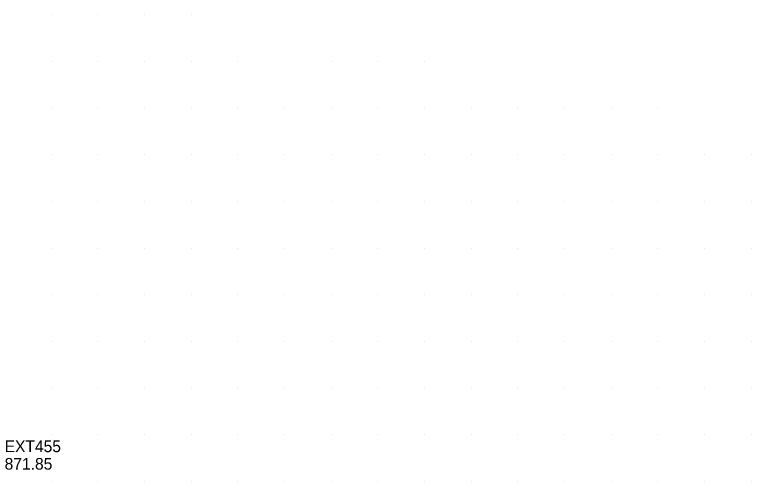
# Model space of a CAD drawing. Extents: x 1762120 to 1766775, y 709485 to 712965.
# Drawn here: x 1762642.2 to 1762800, y 712730 to 712830 of the extents above; entities that cross this region are included whole.
import ezdxf

# ---------------------------------------------------------------- set-up
doc = ezdxf.new("R2010")
doc.units = 0
for name, color, linetype in [('Exist DTM Breakline Cogo Elevation', 7, 'Continuous'), ('Exist DTM Breakline Cogo Number', 7, 'Continuous'), ('Exist DTM QL2 LIDAR Elevation Point', 7, 'Continuous')]:
    doc.layers.add(name, color=color, linetype=linetype)

msp = doc.modelspace()

# ---------------------------------------------------------------- linework, layer by layer
at = {"layer": 'Exist DTM QL2 LIDAR Elevation Point'}
for p, q in [((1762650, 712830), (1762650, 712830)), ((1762660, 712830), (1762660, 712830)), ((1762670, 712830), (1762670, 712830)), ((1762680, 712830), (1762680, 712830)), ((1762650, 712820), (1762650, 712820)), ((1762660, 712820), (1762660, 712820)), ((1762670, 712820), (1762670, 712820)), ((1762680, 712820), (1762680, 712820)), ((1762690, 712820), (1762690, 712820)), ((1762710, 712820), (1762710, 712820)), ((1762720, 712820), (1762720, 712820)), ((1762730, 712820), (1762730, 712820)), ((1762650, 712810), (1762650, 712810)), ((1762660, 712810), (1762660, 712810)), ((1762670, 712810), (1762670, 712810)), ((1762680, 712810), (1762680, 712810)), ((1762690, 712810), (1762690, 712810)), ((1762700, 712810), (1762700, 712810)), ((1762710, 712810), (1762710, 712810)), ((1762720, 712810), (1762720, 712810)), ((1762730, 712810), (1762730, 712810)), ((1762740, 712810), (1762740, 712810)), ((1762750, 712810), (1762750, 712810)), ((1762760, 712810), (1762760, 712810)), ((1762770, 712810), (1762770, 712810)), ((1762780, 712810), (1762780, 712810)), ((1762650, 712800), (1762650, 712800)), ((1762660, 712800), (1762660, 712800)), ((1762670, 712800), (1762670, 712800)), ((1762680, 712800), (1762680, 712800)), ((1762690, 712800), (1762690, 712800)), ((1762700, 712800), (1762700, 712800)), ((1762710, 712800), (1762710, 712800)), ((1762720, 712800), (1762720, 712800)), ((1762730, 712800), (1762730, 712800)), ((1762740, 712800), (1762740, 712800)), ((1762750, 712800), (1762750, 712800)), ((1762760, 712800), (1762760, 712800)), ((1762770, 712800), (1762770, 712800)), ((1762780, 712800), (1762780, 712800)), ((1762790, 712800), (1762790, 712800)), ((1762800, 712800), (1762800, 712800)), ((1762650, 712790), (1762650, 712790)), ((1762660, 712790), (1762660, 712790)), ((1762670, 712790), (1762670, 712790)), ((1762680, 712790), (1762680, 712790)), ((1762690, 712790), (1762690, 712790)), ((1762700, 712790), (1762700, 712790)), ((1762710, 712790), (1762710, 712790)), ((1762720, 712790), (1762720, 712790)), ((1762730, 712790), (1762730, 712790)), ((1762740, 712790), (1762740, 712790)), ((1762750, 712790), (1762750, 712790)), ((1762760, 712790), (1762760, 712790)), ((1762770, 712790), (1762770, 712790)), ((1762780, 712790), (1762780, 712790)), ((1762790, 712790), (1762790, 712790)), ((1762800, 712790), (1762800, 712790)), ((1762650, 712780), (1762650, 712780)), ((1762660, 712780), (1762660, 712780)), ((1762670, 712780), (1762670, 712780)), ((1762680, 712780), (1762680, 712780)), ((1762690, 712780), (1762690, 712780)), ((1762700, 712780), (1762700, 712780)), ((1762710, 712780), (1762710, 712780)), ((1762720, 712780), (1762720, 712780)), ((1762730, 712780), (1762730, 712780)), ((1762740, 712780), (1762740, 712780)), ((1762750, 712780), (1762750, 712780)), ((1762760, 712780), (1762760, 712780)), ((1762770, 712780), (1762770, 712780)), ((1762780, 712780), (1762780, 712780)), ((1762790, 712780), (1762790, 712780)), ((1762800, 712780), (1762800, 712780)), ((1762650, 712770), (1762650, 712770)), ((1762660, 712770), (1762660, 712770)), ((1762670, 712770), (1762670, 712770)), ((1762680, 712770), (1762680, 712770)), ((1762690, 712770), (1762690, 712770)), ((1762700, 712770), (1762700, 712770)), ((1762710, 712770), (1762710, 712770)), ((1762720, 712770), (1762720, 712770)), ((1762730, 712770), (1762730, 712770)), ((1762740, 712770), (1762740, 712770)), ((1762750, 712770), (1762750, 712770)), ((1762760, 712770), (1762760, 712770)), ((1762770, 712770), (1762770, 712770)), ((1762780, 712770), (1762780, 712770)), ((1762790, 712770), (1762790, 712770)), ((1762800, 712770), (1762800, 712770)), ((1762650, 712760), (1762650, 712760)), ((1762660, 712760), (1762660, 712760)), ((1762670, 712760), (1762670, 712760)), ((1762680, 712760), (1762680, 712760)), ((1762690, 712760), (1762690, 712760)), ((1762700, 712760), (1762700, 712760)), ((1762710, 712760), (1762710, 712760)), ((1762720, 712760), (1762720, 712760)), ((1762730, 712760), (1762730, 712760)), ((1762740, 712760), (1762740, 712760)), ((1762750, 712760), (1762750, 712760)), ((1762760, 712760), (1762760, 712760)), ((1762770, 712760), (1762770, 712760)), ((1762780, 712760), (1762780, 712760)), ((1762790, 712760), (1762790, 712760)), ((1762800, 712760), (1762800, 712760)), ((1762650, 712750), (1762650, 712750)), ((1762660, 712750), (1762660, 712750)), ((1762670, 712750), (1762670, 712750)), ((1762680, 712750), (1762680, 712750)), ((1762690, 712750), (1762690, 712750)), ((1762700, 712750), (1762700, 712750)), ((1762710, 712750), (1762710, 712750)), ((1762720, 712750), (1762720, 712750)), ((1762730, 712750), (1762730, 712750)), ((1762740, 712750), (1762740, 712750)), ((1762750, 712750), (1762750, 712750)), ((1762760, 712750), (1762760, 712750)), ((1762770, 712750), (1762770, 712750)), ((1762780, 712750), (1762780, 712750)), ((1762790, 712750), (1762790, 712750)), ((1762800, 712750), (1762800, 712750)), ((1762650, 712740), (1762650, 712740)), ((1762660, 712740), (1762660, 712740)), ((1762670, 712740), (1762670, 712740)), ((1762680, 712740), (1762680, 712740)), ((1762690, 712740), (1762690, 712740)), ((1762700, 712740), (1762700, 712740)), ((1762710, 712740), (1762710, 712740)), ((1762720, 712740), (1762720, 712740)), ((1762730, 712740), (1762730, 712740)), ((1762740, 712740), (1762740, 712740)), ((1762750, 712740), (1762750, 712740)), ((1762760, 712740), (1762760, 712740)), ((1762770, 712740), (1762770, 712740)), ((1762780, 712740), (1762780, 712740)), ((1762790, 712740), (1762790, 712740)), ((1762800, 712740), (1762800, 712740)), ((1762650, 712730), (1762650, 712730)), ((1762660, 712730), (1762660, 712730)), ((1762670, 712730), (1762670, 712730)), ((1762680, 712730), (1762680, 712730)), ((1762690, 712730), (1762690, 712730)), ((1762700, 712730), (1762700, 712730)), ((1762710, 712730), (1762710, 712730)), ((1762720, 712730), (1762720, 712730)), ((1762730, 712730), (1762730, 712730)), ((1762740, 712730), (1762740, 712730)), ((1762750, 712730), (1762750, 712730)), ((1762760, 712730), (1762760, 712730)), ((1762770, 712730), (1762770, 712730)), ((1762780, 712730), (1762780, 712730)), ((1762790, 712730), (1762790, 712730)), ((1762800, 712730), (1762800, 712730))]:
    msp.add_line(p, q, dxfattribs=at)

# ---------------------------------------------------------------- texts
at = {"layer": 'Exist DTM Breakline Cogo Elevation'}
msp.add_text('871.85', height=2.5, dxfattribs=at).set_placement((1762640, 712732.49))
at = {"layer": 'Exist DTM Breakline Cogo Number'}
msp.add_text('EXT455', height=2.5, dxfattribs=at).set_placement((1762640, 712736.24))

doc.saveas('drawing.dxf')
